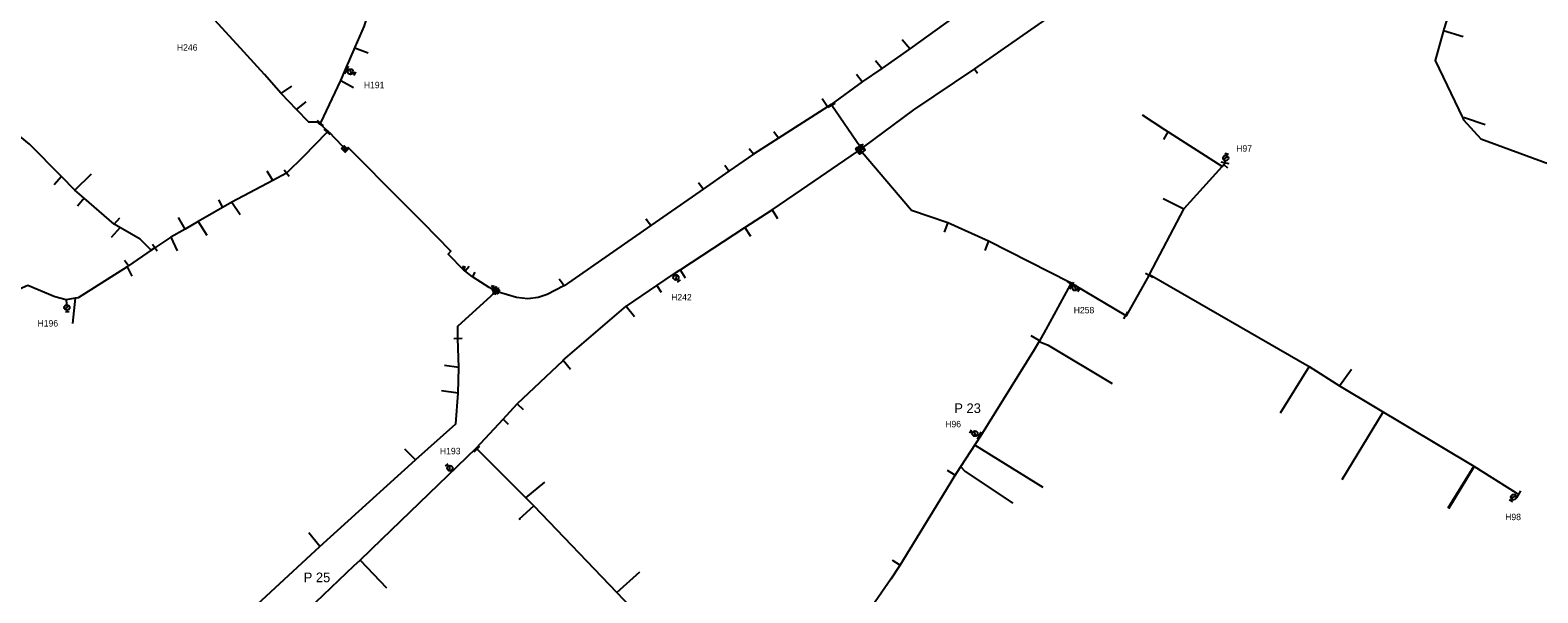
# Model space of a CAD drawing. Extents: x -548873 to -538270, y -1201997 to -1192514.
# Drawn here: x -544932.6 to -544463.9, y -1193452.8 to -1193277.9 of the extents above; entities that cross this region are included whole.
import ezdxf

# ---------------------------------------------------------------- set-up
doc = ezdxf.new("R2010")
doc.units = 0
for name, color, linetype in [('KN_HRAN_STÁTNÍ', 7, 'Continuous'), ('KN_PARC_Č', 7, 'Continuous'), ('KN_VKP_HRAN_SPORNÁ', 7, 'Continuous'), ('PK_PARC_Čv', 7, 'Continuous'), ('Vrstva 29', 7, 'Continuous'), ('Vrstva 39', 7, 'Continuous')]:
    doc.layers.add(name, color=color, linetype=linetype)

# ---------------------------------------------------------------- blocks, each defined once
blk = doc.blocks.new('160')
at = {"layer": 'KN_HRAN_STÁTNÍ'}
blk.add_circle((0, 0), 0.0458, dxfattribs=at)
blk = doc.blocks.new('147')
at = {"layer": 'KN_HRAN_STÁTNÍ'}
blk.add_line((0, 1.27), (0, -1.27), dxfattribs=at)
blk = doc.blocks.new('133')
at = {"layer": 'KN_HRAN_STÁTNÍ'}
for p, q in [((0.28, 0), (0, 0)), ((0.54, 0.58), (1.7, -0.58)), ((1.94, 0), (2.52, 0)), ((2.52, 0.58), (2.52, -0.58))]:
    blk.add_line(p, q, dxfattribs=at)
blk.add_circle((1.11, 0), 0.825, dxfattribs=at)
blk = doc.blocks.new('150')
at = {"layer": 'KN_HRAN_STÁTNÍ'}
blk.add_line((0, 1.27), (0, -1.27), dxfattribs=at)
blk = doc.blocks.new('128')
at = {"layer": 'KN_HRAN_STÁTNÍ'}
for p, q in [((-0.19, 1.06), (-0.43, 1.15)), ((-0.36, 0.84), (-0.19, 1.06)), ((-0.19, 1.06), (-0.02, 1.25)), ((-0.19, 1.06), (0, 0)), ((0.05, 0.95), (-0.19, 1.06)), ((-0.1, 1), (0.41, 0.91)), ((-0.07, 0.82), (0.17, 0.96)), ((0.17, 0.96), (-0.02, 1.13)), ((0.17, 0.96), (0, 0)), ((0.19, 1.21), (0.17, 0.96)), ((0.17, 0.96), (0.38, 1.08)), ((0.36, 0.77), (0.17, 0.96))]:
    blk.add_line(p, q, dxfattribs=at)

msp = doc.modelspace()

# ---------------------------------------------------------------- linework, layer by layer
at = {"layer": 'KN_PARC_Č'}
for points in [[(-544659.112, -1193283.727), (-544661.513, -1193280.935)], [(-544493.202, -1193277.955), (-544487.07, -1193279.853)], [(-544831.65, -1193283.36), (-544827.54, -1193284.902)], [(-544667.892, -1193289.812), (-544669.839, -1193287.4)], [(-544639.019, -1193289.905), (-544638.07, -1193291.208)], [(-544836.075, -1193293.565), (-544832.054, -1193295.733)], [(-544673.96, -1193293.991), (-544675.69, -1193291.705)], [(-544854.6, -1193297.59), (-544854.45, -1193297.46), (-544851.268, -1193295.301)], [(-544684.692, -1193301.692), (-544686.387, -1193299.212)], [(-544849.84, -1193302.54), (-544846.767, -1193300.119)], [(-544562.077, -1193320.252), (-544579.862, -1193308.913), (-544586.839, -1193304.318)], [(-544586.577, -1193304.49), (-544586.536, -1193304.109)], [(-544487.234, -1193305.248), (-544486.666, -1193304.993), (-544480.247, -1193307.194)], [(-544699.984, -1193311.486), (-544701.45, -1193309.525)], [(-544578.896, -1193309.529), (-544580.305, -1193311.882)], [(-544707.721, -1193316.45), (-544709.047, -1193314.743)], [(-544918.758, -1193327.605), (-544913.55, -1193322.6)], [(-544857.127, -1193324.608), (-544858.882, -1193321.755)], [(-544715.382, -1193321.757), (-544716.702, -1193319.936)], [(-544561.539, -1193319.658), (-544560.386, -1193320.703)], [(-544922.842, -1193323.374), (-544925.135, -1193325.95)], [(-544723.43, -1193327.331), (-544724.854, -1193325.396)], [(-544915.784, -1193330.16), (-544917.922, -1193332.605)], [(-544872.724, -1193332.965), (-544873.952, -1193330.633)], [(-544869.934, -1193331.359), (-544867.37, -1193335.206)], [(-544574.004, -1193333.519), (-544580.395, -1193330.301)], [(-544906.485, -1193338.151), (-544904.75, -1193336.273)], [(-544884.472, -1193339.727), (-544886.463, -1193336.121)], [(-544880.404, -1193337.386), (-544877.675, -1193341.66)], [(-544739.676, -1193338.584), (-544741.165, -1193336.624)], [(-544740.984, -1193336.863), (-544740.746, -1193336.679)], [(-544701.978, -1193333.772), (-544700.326, -1193336.402)], [(-544904.639, -1193339.227), (-544907.422, -1193342.311)], [(-544710.425, -1193339.267), (-544708.653, -1193341.944)], [(-544647.303, -1193337.705), (-544648.462, -1193340.725)], [(-544888.925, -1193342.231), (-544886.869, -1193346.455)], [(-544634.664, -1193343.416), (-544635.79, -1193346.341)], [(-544902.01, -1193351.14), (-544903.299, -1193349.52)], [(-544902.473, -1193351.444), (-544901.021, -1193354.357)], [(-544797.49, -1193352.73), (-544797.41, -1193352.68), (-544796.157, -1193351.267)], [(-544795.09, -1193354.55), (-544795.02, -1193354.47), (-544794.247, -1193353.158)], [(-544766.653, -1193357.339), (-544768.171, -1193355.289)], [(-544730.542, -1193352.358), (-544728.994, -1193354.907)], [(-544737.821, -1193357.286), (-544736.432, -1193359.343)], [(-544918.647, -1193361.246), (-544919.464, -1193369.077)], [(-544747.296, -1193363.708), (-544744.728, -1193366.929)], [(-544618.82, -1193374.46), (-544618.96, -1193374.36), (-544621.408, -1193372.922)], [(-544618.947, -1193374.699), (-544616.09, -1193375.78), (-544596.194, -1193387.694)], [(-544799.345, -1193382.726), (-544803.827, -1193382.105)], [(-544766.914, -1193380.528), (-544764.642, -1193383.241)], [(-544534.985, -1193382.432), (-544543.99, -1193396.96)], [(-544525.516, -1193388.459), (-544521.822, -1193383.237)], [(-544596.481, -1193387.522), (-544596.612, -1193387.831)], [(-544799.558, -1193390.689), (-544804.739, -1193389.972)], [(-544781.201, -1193394.085), (-544779.386, -1193395.77)], [(-544511.99, -1193396.561), (-544524.89, -1193417.682)], [(-544785.581, -1193398.79), (-544784.024, -1193400.397)], [(-544639.005, -1193406.848), (-544617.772, -1193419.961)], [(-544812.836, -1193411.458), (-544816.091, -1193408.135)], [(-544645.042, -1193416.246), (-544645.3, -1193416.09), (-544647.388, -1193414.825)], [(-544643.377, -1193413.514), (-544641.95, -1193415.13), (-544627.084, -1193424.941)], [(-544483.835, -1193413.425), (-544491.866, -1193426.538)], [(-544483.675, -1193413.526), (-544491.654, -1193426.679)], [(-544778.557, -1193423.289), (-544772.629, -1193418.369)], [(-544776.054, -1193425.797), (-544780.729, -1193430.02)], [(-544780.506, -1193429.819), (-544780.393, -1193430.096)], [(-544842.56, -1193438.427), (-544845.948, -1193434.116)], [(-544830.065, -1193442.622), (-544821.882, -1193451.281)], [(-544662.247, -1193444.178), (-544662.38, -1193444.09), (-544664.31, -1193442.82), (-544664.574, -1193442.646)], [(-544750.274, -1193452.675), (-544743.13, -1193446.242)]]:
    msp.add_lwpolyline(points, dxfattribs=at)
at = {"layer": 'KN_VKP_HRAN_SPORNÁ'}
for points in [[(-544484.41, -1193186.865), (-544484.5, -1193186.955), (-544492.023, -1193194.518), (-544510.839, -1193213.432), (-544513.794, -1193216.753), (-544519.47, -1193233.363), (-544520.63, -1193236.758), (-544515.481, -1193242.28), (-544504.791, -1193253.747), (-544490.482, -1193269.207), (-544493.088, -1193277.551), (-544493.202, -1193277.955), (-544495.843, -1193287.359), (-544487.234, -1193305.248), (-544486.992, -1193305.75), (-544481.617, -1193311.689), (-544453.414, -1193322.024), (-544452.85, -1193322.231), (-544437.022, -1193308.689), (-544436.391, -1193308.88)], [(-544842.37, -1193306.78), (-544842.26, -1193306.65), (-544836.075, -1193293.565), (-544834.587, -1193290.133), (-544831.585, -1193283.21), (-544828.691, -1193276.537), (-544828.668, -1193276.468), (-544823.113, -1193259.542), (-544819.838, -1193250.526), (-544817.387, -1193243.768), (-544813.71, -1193236.351), (-544812.402, -1193235.968), (-544797.18, -1193239.166), (-544785.987, -1193240.585), (-544785.011, -1193239.406), (-544784.953, -1193235.765), (-544785.084, -1193226.716), (-544784.98, -1193215.478), (-544787.684, -1193208.541), (-544790.928, -1193200.123), (-544794.096, -1193191.903)], [(-544842.82, -1193306.87), (-544843.31, -1193306.48), (-544845.95, -1193306.52), (-544849.84, -1193302.54), (-544854.6, -1193297.59), (-544859.76, -1193291.71), (-544868.41, -1193282.27), (-544876.48, -1193273.39), (-544880.25, -1193269.19), (-544880.94, -1193268.31), (-544881.3, -1193267.57), (-544881.46, -1193266.67), (-544881.39, -1193262.45), (-544881.42, -1193261.36), (-544881.11, -1193260.99)], [(-544635.144, -1193266.278), (-544659.112, -1193283.727), (-544667.892, -1193289.812), (-544673.961, -1193293.991), (-544683.581, -1193300.981)], [(-544600.704, -1193266.516), (-544600.983, -1193266.801), (-544608.484, -1193270.417), (-544616.683, -1193274.37), (-544616.853, -1193274.488), (-544639.019, -1193289.905), (-544657.955, -1193302.649), (-544673.656, -1193314.224), (-544673.86, -1193314.379)], [(-544683.581, -1193300.981), (-544684.692, -1193301.692), (-544699.984, -1193311.486), (-544707.723, -1193316.452), (-544715.382, -1193321.757), (-544723.428, -1193327.33), (-544726.857, -1193329.705), (-544739.675, -1193338.583), (-544766.653, -1193357.339), (-544766.705, -1193357.375), (-544771.84, -1193360.105), (-544774.651, -1193361.016), (-544777.897, -1193361.372), (-544781.419, -1193361.016), (-544787.024, -1193359.312), (-544787.508, -1193359.031)], [(-544683.581, -1193300.981), (-544683.439, -1193301.187)], [(-544683.439, -1193301.187), (-544674.542, -1193314.081)], [(-544894.971, -1193346.319), (-544898.446, -1193342.837), (-544906.485, -1193338.151), (-544915.784, -1193330.16), (-544918.758, -1193327.605), (-544922.884, -1193323.33), (-544932.801, -1193313.36), (-544940.396, -1193307.148)], [(-544842.61, -1193307.05), (-544842.82, -1193306.87)], [(-544842.61, -1193307.05), (-544842.54, -1193306.97), (-544842.37, -1193306.78)], [(-544840.04, -1193309.33), (-544842.61, -1193307.05)], [(-544840.28, -1193309.61), (-544840.46, -1193309.81), (-544847.646, -1193317.182), (-544852.9, -1193322.38)], [(-544840.04, -1193309.33), (-544840.17, -1193309.48), (-544840.28, -1193309.61)], [(-544834.9, -1193315.35), (-544835.1, -1193314.73), (-544835.24, -1193314.29), (-544837.77, -1193311.54), (-544839.4, -1193309.81), (-544839.74, -1193309.61), (-544840.04, -1193309.33)], [(-544797.75, -1193352.49), (-544802.68, -1193347.49), (-544801.83, -1193346.54), (-544810.47, -1193337.79), (-544814.7, -1193333.53), (-544818.92, -1193329.27), (-544823.18, -1193325.01), (-544827.39, -1193320.71), (-544833.8, -1193314.32), (-544834.88, -1193315.31), (-544834.9, -1193315.35)], [(-544793.955, -1193407.872), (-544785.581, -1193398.79), (-544781.201, -1193394.085), (-544781.177, -1193394.06), (-544766.938, -1193380.549), (-544766.914, -1193380.528), (-544747.296, -1193363.708), (-544747.255, -1193363.673), (-544737.819, -1193357.284), (-544732.645, -1193353.718), (-544730.543, -1193352.358), (-544730.378, -1193352.246), (-544710.425, -1193339.267), (-544701.978, -1193333.772), (-544692.804, -1193327.484), (-544675.457, -1193315.595), (-544674.994, -1193315.242)], [(-544674.994, -1193315.242), (-544674.604, -1193314.945)], [(-544674.173, -1193314.617), (-544674.604, -1193314.945)], [(-544674.604, -1193314.945), (-544674.364, -1193315.265)], [(-544674.542, -1193314.081), (-544674.173, -1193314.617)], [(-544674.364, -1193315.265), (-544673.968, -1193315.791), (-544658.628, -1193333.856), (-544647.305, -1193337.704), (-544647.289, -1193337.71), (-544634.665, -1193343.416), (-544609.4, -1193356.23), (-544608.9, -1193356.52)], [(-544673.86, -1193314.379), (-544674.173, -1193314.617)], [(-544852.9, -1193322.38), (-544857.127, -1193324.608), (-544869.912, -1193331.347), (-544880.404, -1193337.386), (-544884.473, -1193339.728), (-544888.925, -1193342.231), (-544893.895, -1193345.591)], [(-544584.583, -1193353.895), (-544574.004, -1193333.519), (-544573.893, -1193333.306), (-544562.082, -1193320.257), (-544561.54, -1193319.658), (-544561.306, -1193319.4)], [(-544894.971, -1193346.319), (-544902.009, -1193351.139), (-544902.243, -1193351.299), (-544902.473, -1193351.444), (-544917.739, -1193361.092), (-544918.647, -1193361.246), (-544921.384, -1193361.71), (-544924.97, -1193360.791), (-544933.315, -1193357.241), (-544939.492, -1193359.951), (-544943.546, -1193361.73)], [(-544893.895, -1193345.591), (-544894.971, -1193346.319)], [(-544788.78, -1193358.52), (-544789.17, -1193358.29), (-544789.93, -1193357.85), (-544795.09, -1193354.55), (-544797.49, -1193352.73), (-544797.75, -1193352.49)], [(-544592, -1193366.56), (-544591.833, -1193366.661), (-544584.736, -1193354.152)], [(-544584.736, -1193354.152), (-544584.583, -1193353.895)], [(-544584.583, -1193353.895), (-544534.985, -1193382.432), (-544525.516, -1193388.459), (-544483.835, -1193413.425), (-544470.634, -1193421.7), (-544469.903, -1193422.145)], [(-544799.63, -1193373.727), (-544799.708, -1193369.957), (-544788.13, -1193359.415), (-544787.979, -1193359.159)], [(-544788.145, -1193358.653), (-544788.78, -1193358.52)], [(-544787.801, -1193358.858), (-544788.145, -1193358.653)], [(-544787.979, -1193359.159), (-544787.801, -1193358.858)], [(-544787.508, -1193359.031), (-544787.801, -1193358.858)], [(-544609.09, -1193356.73), (-544609.29, -1193357.09), (-544616.87, -1193370.9), (-544618.32, -1193373.547)], [(-544608.9, -1193356.52), (-544609.09, -1193356.73)], [(-544608.9, -1193356.52), (-544608.02, -1193357.08), (-544592, -1193366.56)], [(-544925.975, -1193513.316), (-544922.268, -1193510.197), (-544913.832, -1193503.099), (-544898.092, -1193489.854), (-544898.064, -1193489.828), (-544894.197, -1193486.235), (-544885.192, -1193477.869), (-544873.034, -1193466.62), (-544842.561, -1193438.428), (-544812.835, -1193411.457), (-544812.726, -1193411.357), (-544800.327, -1193400.27), (-544799.558, -1193390.689), (-544799.344, -1193382.742), (-544799.63, -1193373.727)], [(-544618.32, -1193373.547), (-544618.82, -1193374.46), (-544619.09, -1193374.97), (-544620.49, -1193377.221), (-544637.21, -1193404.11), (-544643.44, -1193413.61), (-544645.44, -1193416.9), (-544646.687, -1193418.924), (-544662.3, -1193444.264), (-544665.07, -1193448.54), (-544670.89, -1193456.94), (-544680.37, -1193467.03), (-544684.479, -1193471.289), (-544686.79, -1193473.29), (-544703.94, -1193490), (-544709.66, -1193495.02)], [(-544823.294, -1193436.106), (-544793.955, -1193407.872)], [(-544793.955, -1193407.872), (-544793.743, -1193408.084)], [(-544793.743, -1193408.084), (-544778.557, -1193423.289), (-544776.054, -1193425.797), (-544750.274, -1193452.675), (-544742.226, -1193461.066), (-544739.778, -1193463.618), (-544717.339, -1193486.981), (-544710.13, -1193494.82)], [(-544881.976, -1193490.354), (-544881.575, -1193489.989), (-544843.851, -1193455.663), (-544831.902, -1193444.36), (-544830.172, -1193442.723), (-544830.065, -1193442.622), (-544823.294, -1193436.106)]]:
    msp.add_lwpolyline(points, dxfattribs=at)
at = {"layer": 'PK_PARC_Čv'}
for points in [[(-544834.587, -1193290.133), (-544834.076, -1193290.334)], [(-544835.812, -1193314.694), (-544834.987, -1193313.847), (-544833.906, -1193315.016), (-544834.716, -1193315.811), (-544835.812, -1193314.694)], [(-544676.01, -1193314.86), (-544674.21, -1193313.49), (-544673.02, -1193315.07), (-544674.82, -1193316.44), (-544676.01, -1193314.86)], [(-544561.306, -1193319.4), (-544561.164, -1193318.737)], [(-544732.645, -1193353.718), (-544732.524, -1193353.877)], [(-544788.14, -1193357.9), (-544786.694, -1193358.753), (-544787.355, -1193359.873), (-544788.801, -1193359.02), (-544788.14, -1193357.9)], [(-544609.29, -1193357.09), (-544608.87, -1193357.29), (-544608.69, -1193357.41)], [(-544921.384, -1193361.71), (-544921.286, -1193362.994)], [(-544637.21, -1193404.11), (-544637.61, -1193403.92), (-544637.88, -1193403.8)], [(-544801.296, -1193414.937), (-544801.355, -1193414.875)], [(-544470.634, -1193421.7), (-544470.871, -1193422.083)]]:
    msp.add_lwpolyline(points, dxfattribs=at)

# ---------------------------------------------------------------- block references
for name, p, xscale, yscale, rotation in [('150', (-544834.305, -1193290.244), 1.0275072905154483, 1.027507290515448, -24.689105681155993), ('133', (-544834.076, -1193290.334), 1.0275072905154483, 1.027507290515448, -24.689105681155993), ('133', (-544561.164, -1193318.737), 1.0000000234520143, 1.0000000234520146, 78.0000006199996), ('150', (-544561.243, -1193319.107), 1.0000000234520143, 1.0000000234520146, 78.0000006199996), ('133', (-544732.524, -1193353.877), 1.000000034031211, 1.0000000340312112, -51.999999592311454), ('150', (-544608.87, -1193357.29), 1.0037042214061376, 1.0037042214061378, -29.379208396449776), ('133', (-544608.69, -1193357.41), 0.9999999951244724, 0.9999999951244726, -33.000001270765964), ('133', (-544921.286, -1193362.994), 1.000000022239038, 1.0000000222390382, -85.00000001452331), ('133', (-544637.88, -1193403.8), 1.0225848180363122, 1.0225848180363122, 154.18102564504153), ('150', (-544637.61, -1193403.92), 1.019856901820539, 1.0198569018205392, -26.393983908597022), ('133', (-544801.355, -1193414.875), 1.0000000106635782, 1.0000000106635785, 134.00000165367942), ('133', (-544470.871, -1193422.083), 1.0000000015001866, 1.0000000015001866, -120.99999982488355)]:
    msp.add_blockref(name, p, dxfattribs=dict(at, xscale=xscale, yscale=yscale, rotation=rotation))
at = {"layer": 'Vrstva 29'}
for name, p, xscale, yscale, rotation in [('147', (-544683.439, -1193301.187), 1.0000000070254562, 1.0000000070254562, 118.99999892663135), ('160', (-544683.581, -1193300.981), 1.000000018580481, 1.000000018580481, 35.000000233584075), ('147', (-544842.37, -1193306.78), 1.0000000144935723, 1.0000000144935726, -130.99999910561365), ('160', (-544842.82, -1193306.87), 1.000000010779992, 1.0000000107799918, 141.00000108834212), ('160', (-544842.61, -1193307.05), 1.0000000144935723, 1.0000000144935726, 139.00000089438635), ('147', (-544840.28, -1193309.61), 1.0000000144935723, 1.0000000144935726, -130.99999910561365), ('160', (-544840.04, -1193309.33), 1.0000000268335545, 1.0000000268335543, -86.00000028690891), ('147', (-544674.542, -1193314.081), 1.000000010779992, 1.0000000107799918, 128.99999891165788), ('147', (-544673.86, -1193314.379), 1.000000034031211, 1.0000000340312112, 38.000000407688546), ('160', (-544834.9, -1193315.35), 1.0000000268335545, 1.0000000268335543, 176.00000028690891), ('147', (-544674.994, -1193315.242), 1.000000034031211, 1.0000000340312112, -141.99999959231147), ('147', (-544674.364, -1193315.265), 0.9999999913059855, 0.9999999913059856, 127.00000193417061), ('160', (-544674.604, -1193314.945), 1.000191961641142, 1.000191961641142, 82.91099886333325), ('160', (-544674.173, -1193314.617), 1.0000000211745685, 1.0000000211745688, -98.99999960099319), ('147', (-544852.9, -1193322.38), 0.9999999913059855, 0.9999999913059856, -142.99999806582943), ('160', (-544561.306, -1193319.4), 1.0000000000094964, 1.0000000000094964, 47.99999869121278), ('160', (-544894.971, -1193346.319), 1.000000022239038, 1.0000000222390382, -94.99999998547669), ('147', (-544893.895, -1193345.591), 1.000000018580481, 1.000000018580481, -144.99999976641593), ('160', (-544797.75, -1193352.49), 1.0000000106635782, 1.0000000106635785, 135.99999834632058), ('147', (-544609.09, -1193356.73), 1.000000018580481, 1.000000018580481, -125.00000023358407), ('147', (-544584.736, -1193354.152), 0.9999999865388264, 0.9999999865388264, -120.00000044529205), ('160', (-544584.583, -1193353.895), 0.9999999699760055, 0.9999999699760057, 106.99999966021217), ('147', (-544787.979, -1193359.159), 0.9999999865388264, 0.9999999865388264, -120.00000044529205), ('160', (-544788.78, -1193358.52), 1.0275072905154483, 1.027507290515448, 155.31089431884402), ('147', (-544788.145, -1193358.653), 1.0275072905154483, 1.027507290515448, 155.31089431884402), ('147', (-544787.508, -1193359.031), 0.9999999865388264, 0.9999999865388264, 149.99999955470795), ('160', (-544787.801, -1193358.858), 0.9999999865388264, 0.9999999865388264, 149.99999955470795), ('160', (-544608.9, -1193356.52), 1.0092050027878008, 1.0092050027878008, -168.88308178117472), ('147', (-544592, -1193366.56), 0.9999999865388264, 0.9999999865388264, 149.99999955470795), ('147', (-544799.63, -1193373.727), 1.00000001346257, 1.0000000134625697, 91.99999990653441), ('160', (-544618.32, -1193373.547), 0.9999999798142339, 0.9999999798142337, -118.00000133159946), ('147', (-544793.743, -1193408.084), 1.0000000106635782, 1.0000000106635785, 135.99999834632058), ('147', (-544469.903, -1193422.145), 1.0000000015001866, 1.0000000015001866, -30.99999982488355), ('160', (-544823.294, -1193436.106), 0.999999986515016, 0.9999999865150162, 74.99999987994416)]:
    msp.add_blockref(name, p, dxfattribs=dict(at, xscale=xscale, yscale=yscale, rotation=rotation))
at = {"layer": 'Vrstva 29', "rotation": 180}
msp.add_blockref('160', (-544793.955, -1193407.872), dxfattribs=at)
at = {"layer": 'Vrstva 39'}
for p in [(-544834.9, -1193315.35), (-544797.75, -1193352.49), (-544788.78, -1193358.52)]:
    msp.add_blockref('128', p, dxfattribs=at)

# ---------------------------------------------------------------- texts
at = {"layer": 'PK_PARC_Čv'}
for s, height, p in [('H246', 2, (-544887, -1193284.263)), ('H191', 2, (-544828.876, -1193295.934)), ('H97', 2, (-544557.674, -1193315.647)), ('H242', 2, (-544733.344, -1193361.927)), ('H258', 2, (-544608.19, -1193365.92)), ('H196', 2, (-544930.316, -1193370.014)), ('P 23', 3, (-544645.31, -1193396.91)), ('H96', 2, (-544648.13, -1193401.34)), ('H193', 2, (-544805.225, -1193409.735)), ('H98', 2, (-544474.061, -1193430.213)), ('P 25', 3, (-544847.568, -1193449.505))]:
    msp.add_text(s, height=height, dxfattribs=at).set_placement(p)

doc.saveas('drawing.dxf')
